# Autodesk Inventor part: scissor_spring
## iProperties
Shininess: 0.0
Length Units: 11269
Angle Units: 11279
Time Units: 11290
Mass Units: 11283
Length Display Precision: 3
Angle Display Precision: 2
Compacted: True
Manager: Lebovitz
Company: Autodesk
Created: 2000-05
Part Number: scissor_spring
Document SubType Name: Modeling
Designer: The PD Team
Project: Inventor Samples
Density: 1 g/cm^3
Density: 0.0
Volumn: 0.0
Area: 0.0
PropertySet Name: Model Information
Control State: 0
Master: False
Checked Out: False
Author: The PD Team
Revision Number: A
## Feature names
1. Extrusion2
